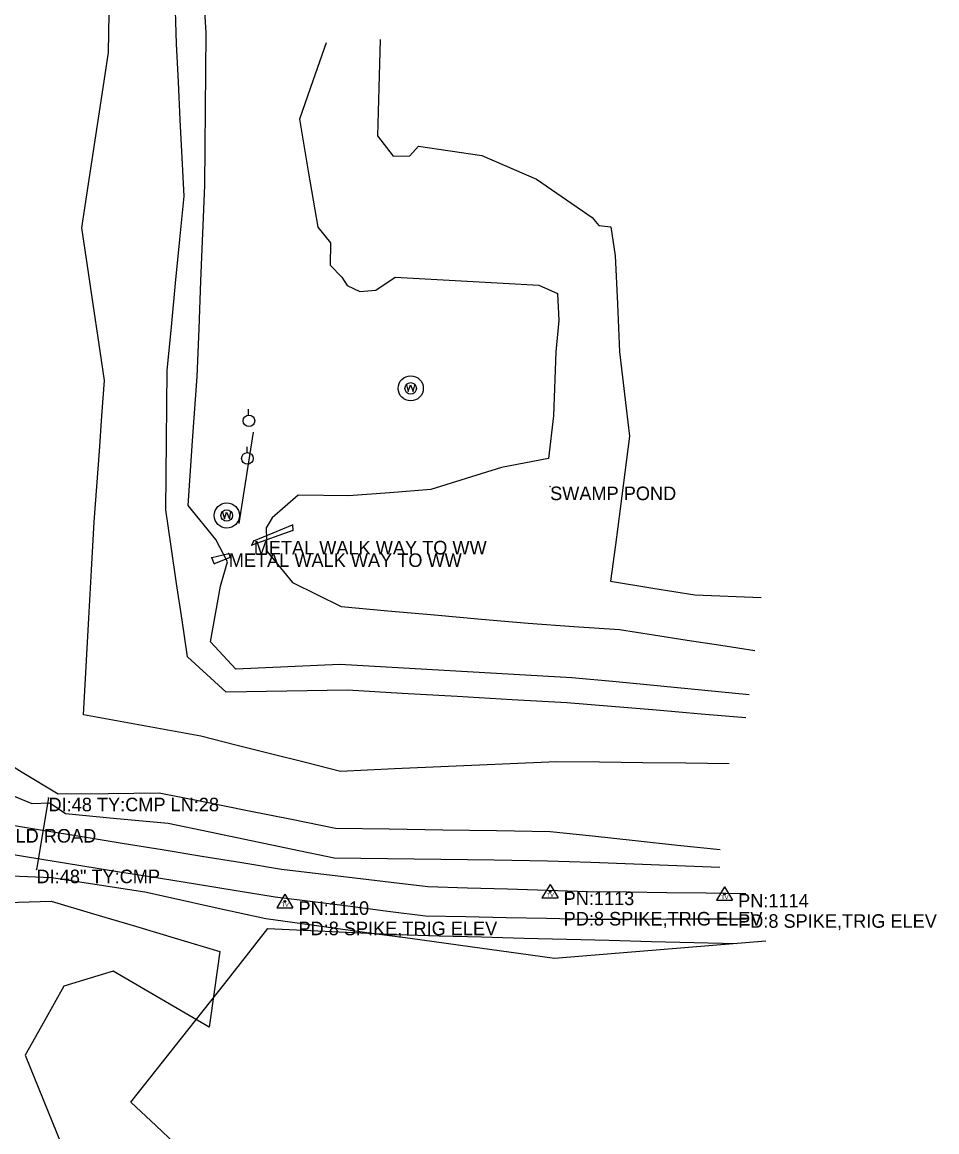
# Model space of a CAD drawing. Extents: x 1445297 to 1476720, y 2042269 to 2057889.
# Drawn here: x 1446166.6 to 1446503.5, y 2044126.9 to 2044535.6 of the extents above; entities that cross this region are included whole.
import ezdxf

# ---------------------------------------------------------------- set-up
doc = ezdxf.new("R2010")
doc.units = 0
for name, color, linetype in [('S_DITCHLINE', 7, 'Continuous'), ('S_DRG_PT_SYM', 7, 'Continuous'), ('S_DRIVEWAY', 7, 'Continuous'), ('S_MISC_STRUCTURES', 7, 'Continuous'), ('S_MISC_STRUCTURES_ANNOT', 7, 'Continuous'), ('S_MSC_PT_SYM', 7, 'Continuous'), ('S_SECONDARY_CTL', 7, 'Continuous'), ('S_SECONDARY_CTL_ANNOT', 7, 'Continuous'), ('S_SIDE_DRAIN', 7, 'Continuous'), ('S_SIDE_DRAIN_ANNOT', 7, 'Continuous'), ('S_STREAM', 7, 'Continuous'), ('S_SURVEY_TEXT_ANNOT', 7, 'Continuous'), ('S_TREE', 7, 'Continuous'), ('S_UTILITY_POLE', 7, 'Continuous'), ('S_WATER_WELL', 7, 'Continuous')]:
    doc.layers.add(name, color=color, linetype=linetype)

msp = doc.modelspace()

# ---------------------------------------------------------------- linework, layer by layer
at = {"layer": 'S_DITCHLINE'}
for points in [[(1446426.97, 2044262.5), (1446411.07, 2044262.69), (1446395.16, 2044262.88), (1446379.26, 2044263.07), (1446363.35, 2044263.26), (1446343.47, 2044262.37), (1446323.58, 2044261.47), (1446303.7, 2044260.58), (1446283.82, 2044259.69), (1446270.96, 2044262.92), (1446258.11, 2044266.15), (1446245.26, 2044269.38), (1446232.4, 2044272.61), (1446210.83, 2044276.54), (1446189.26, 2044280.46), (1446190.23, 2044298.26), (1446191.19, 2044316.06), (1446192.16, 2044333.85), (1446193.12, 2044351.65), (1446194.09, 2044364.66), (1446195.05, 2044377.67), (1446196.01, 2044390.68), (1446196.98, 2044403.68), (1446194.89, 2044417.75), (1446192.8, 2044431.81), (1446190.7, 2044445.87), (1446188.61, 2044459.94), (1446191.07, 2044476.06), (1446193.52, 2044492.19), (1446195.98, 2044508.31), (1446198.43, 2044524.43), (1446198.76, 2044546.08)], [(1446433.14, 2044279.42), (1446416.67, 2044280.8), (1446400.19, 2044282.18), (1446383.71, 2044283.56), (1446367.23, 2044284.94), (1446347.02, 2044286.09), (1446326.81, 2044287.25), (1446306.6, 2044288.41), (1446286.39, 2044289.56), (1446264.07, 2044289.19), (1446241.76, 2044288.82), (1446227.48, 2044301.91), (1446225.5, 2044315.43), (1446223.52, 2044328.94), (1446221.53, 2044342.46), (1446219.55, 2044355.98), (1446219.67, 2044368.82), (1446219.79, 2044381.66), (1446219.91, 2044394.5), (1446220.04, 2044407.35), (1446221.59, 2044423.41), (1446223.14, 2044439.48), (1446224.69, 2044455.54), (1446226.24, 2044471.6), (1446225.55, 2044485.63), (1446224.86, 2044499.66), (1446224.16, 2044513.69), (1446223.47, 2044527.71), (1446222.82, 2044547.92)], [(1446423.68, 2044230.76), (1446408.02, 2044232.43), (1446392.37, 2044234.11), (1446376.72, 2044235.78), (1446361.06, 2044237.46), (1446341.3, 2044237.77), (1446321.55, 2044238.08), (1446301.79, 2044238.38), (1446282.03, 2044238.69), (1446265.79, 2044241.93), (1446249.55, 2044245.17), (1446233.31, 2044248.42), (1446217.07, 2044251.66), (1446198.45, 2044251.44), (1446179.83, 2044251.23), (1446166.64, 2044259.28), (1446153.45, 2044267.34)], [(1446161.07, 2044211.42), (1446177.35, 2044211.9), (1446192.85, 2044207.25), (1446208.35, 2044202.61), (1446223.85, 2044197.96), (1446239.36, 2044193.31), (1446237.45, 2044179.38), (1446235.53, 2044165.45), (1446217.86, 2044175.79), (1446200.18, 2044186.13), (1446181.98, 2044180.52), (1446174.87, 2044167.83), (1446167.75, 2044155.15), (1446174.36, 2044138.84), (1446180.96, 2044122.53)]]:
    msp.add_lwpolyline(points, dxfattribs=at)
at = {"layer": 'S_DRG_PT_SYM'}
for points in [[(1446176.33, 2044249.98), (1446176.33, 2044250.03), (1446176.33, 2044249.98), (1446176.28, 2044249.98), (1446176.33, 2044249.98), (1446176.33, 2044249.93), (1446176.33, 2044249.98), (1446176.38, 2044249.98)], [(1446171.93, 2044223.49), (1446171.93, 2044223.54), (1446171.93, 2044223.49), (1446171.88, 2044223.49), (1446171.93, 2044223.49), (1446171.93, 2044223.44), (1446171.93, 2044223.49), (1446171.98, 2044223.49)]]:
    msp.add_lwpolyline(points, dxfattribs=at)
at = {"layer": 'S_DRIVEWAY'}
for points in [[(1446120.2, 2044252.54), (1446131.57, 2044246.1), (1446144.72, 2044242.87), (1446159.4, 2044240.47), (1446174.09, 2044238.08), (1446188.77, 2044235.68), (1446203.45, 2044233.29), (1446218.13, 2044230.89), (1446232.81, 2044228.5), (1446247.49, 2044226.1), (1446262.18, 2044223.71), (1446275.63, 2044222.1), (1446289.08, 2044220.5), (1446302.53, 2044218.89), (1446315.98, 2044217.29), (1446330.69, 2044216.84), (1446345.39, 2044216.38), (1446360.1, 2044215.93), (1446374.81, 2044215.47), (1446389.39, 2044215.28), (1446403.98, 2044215.08), (1446418.56, 2044214.89), (1446433.15, 2044214.69)], [(1446121.63, 2044225.44), (1446145.27, 2044231.95), (1446159.59, 2044229.64), (1446173.9, 2044227.34), (1446188.22, 2044225.04), (1446202.53, 2044222.73), (1446216.85, 2044220.43), (1446231.17, 2044218.12), (1446245.48, 2044215.82), (1446259.8, 2044213.52), (1446273.64, 2044211.76), (1446287.48, 2044209.99), (1446301.32, 2044208.23), (1446315.16, 2044206.47), (1446330.01, 2044206.17), (1446344.87, 2044205.87), (1446359.72, 2044205.56), (1446374.57, 2044205.26), (1446389.23, 2044205.3), (1446403.89, 2044205.33), (1446418.55, 2044205.37), (1446433.2, 2044205.41)]]:
    msp.add_lwpolyline(points, dxfattribs=at)
at = {"layer": 'S_MISC_STRUCTURES'}
for p, q in [((1446251.89, 2044344.6), (1446266.14, 2044350.45)), ((1446266.14, 2044350.45), (1446266.29, 2044348.4)), ((1446266.29, 2044348.4), (1446251.17, 2044342.95)), ((1446251.17, 2044342.95), (1446251.89, 2044344.6)), ((1446236.49, 2044338.49), (1446242.71, 2044339.98)), ((1446237.36, 2044336.14), (1446236.49, 2044338.49)), ((1446243.28, 2044338.44), (1446237.36, 2044336.14)), ((1446242.71, 2044339.98), (1446243.28, 2044338.44))]:
    msp.add_line(p, q, dxfattribs=at)
at = {"layer": 'S_MSC_PT_SYM'}
for points in [[(1446361.05, 2044364.59), (1446361.05, 2044364.64), (1446361.05, 2044364.59), (1446361, 2044364.59), (1446361.05, 2044364.59), (1446361.05, 2044364.54), (1446361.05, 2044364.59), (1446361.1, 2044364.59)], [(1446266.14, 2044350.45), (1446266.14, 2044350.5), (1446266.14, 2044350.45), (1446266.09, 2044350.45), (1446266.14, 2044350.45), (1446266.14, 2044350.4), (1446266.14, 2044350.45), (1446266.19, 2044350.45)], [(1446266.29, 2044348.4), (1446266.29, 2044348.45), (1446266.29, 2044348.4), (1446266.24, 2044348.4), (1446266.29, 2044348.4), (1446266.29, 2044348.35), (1446266.29, 2044348.4), (1446266.34, 2044348.4)], [(1446251.17, 2044342.95), (1446251.17, 2044343), (1446251.17, 2044342.95), (1446251.12, 2044342.95), (1446251.17, 2044342.95), (1446251.17, 2044342.9), (1446251.17, 2044342.95), (1446251.22, 2044342.95)], [(1446251.89, 2044344.6), (1446251.89, 2044344.65), (1446251.89, 2044344.6), (1446251.84, 2044344.6), (1446251.89, 2044344.6), (1446251.89, 2044344.55), (1446251.89, 2044344.6), (1446251.94, 2044344.6)], [(1446236.49, 2044338.49), (1446236.49, 2044338.54), (1446236.49, 2044338.49), (1446236.44, 2044338.49), (1446236.49, 2044338.49), (1446236.49, 2044338.44), (1446236.49, 2044338.49), (1446236.54, 2044338.49)], [(1446242.71, 2044339.98), (1446242.71, 2044340.03), (1446242.71, 2044339.98), (1446242.66, 2044339.98), (1446242.71, 2044339.98), (1446242.71, 2044339.93), (1446242.71, 2044339.98), (1446242.76, 2044339.98)], [(1446243.28, 2044338.44), (1446243.28, 2044338.49), (1446243.28, 2044338.44), (1446243.23, 2044338.44), (1446243.28, 2044338.44), (1446243.28, 2044338.39), (1446243.28, 2044338.44), (1446243.33, 2044338.44)], [(1446237.36, 2044336.14), (1446237.36, 2044336.19), (1446237.36, 2044336.14), (1446237.31, 2044336.14), (1446237.36, 2044336.14), (1446237.36, 2044336.09), (1446237.36, 2044336.14), (1446237.41, 2044336.14)]]:
    msp.add_lwpolyline(points, dxfattribs=at)
at = {"layer": 'S_SECONDARY_CTL'}
for p, q in [((1446263.37, 2044214.44), (1446260.36, 2044209.48)), ((1446263.37, 2044214.44), (1446266.32, 2044209.48)), ((1446361.04, 2044218.02), (1446358.03, 2044213.07)), ((1446361.04, 2044218.02), (1446363.98, 2044213.07)), ((1446425.29, 2044217.18), (1446422.28, 2044212.23)), ((1446425.29, 2044217.18), (1446428.24, 2044212.23)), ((1446358.03, 2044213.07), (1446363.98, 2044213.07)), ((1446422.28, 2044212.23), (1446428.24, 2044212.23)), ((1446260.36, 2044209.48), (1446266.32, 2044209.48))]:
    msp.add_line(p, q, dxfattribs=at)
for centre, radius in [((1446361.04, 2044215.41), 0.311), ((1446361.04, 2044215.41), 0.183), ((1446361.04, 2044215.41), 0.103), ((1446425.29, 2044214.57), 0.311), ((1446425.29, 2044214.57), 0.183), ((1446425.29, 2044214.57), 0.103), ((1446263.37, 2044211.83), 0.311), ((1446263.37, 2044211.83), 0.183), ((1446263.37, 2044211.83), 0.103)]:
    msp.add_circle(centre, radius, dxfattribs=at)
at = {"layer": 'S_SIDE_DRAIN'}
msp.add_line((1446176.33, 2044249.98), (1446171.93, 2044223.49), dxfattribs=at)
at = {"layer": 'S_STREAM'}
for points in [[(1446434.39, 2044287.91), (1446418.05, 2044289.48), (1446401.7, 2044291.05), (1446385.35, 2044292.62), (1446369.01, 2044294.18), (1446347.67, 2044295.4), (1446326.33, 2044296.62), (1446304.99, 2044297.83), (1446283.65, 2044299.05), (1446264.46, 2044298.19), (1446245.26, 2044297.33), (1446236.03, 2044307.42), (1446239.68, 2044327.94), (1446242.24, 2044336.82), (1446237.92, 2044345.13), (1446227.77, 2044357.64), (1446229.41, 2044381.4), (1446231.05, 2044405.16), (1446231.76, 2044422.75), (1446232.48, 2044440.34), (1446233.19, 2044457.93), (1446233.9, 2044475.51), (1446234.03, 2044489.56), (1446234.15, 2044503.61), (1446234.27, 2044517.66), (1446234.4, 2044531.71), (1446233.18, 2044551.58)], [(1446298.49, 2044529.24), (1446297.99, 2044511.49), (1446297.49, 2044493.73), (1446303.31, 2044486.3), (1446309.44, 2044486.36), (1446312.59, 2044489.99), (1446335.95, 2044486.5), (1446356.05, 2044477.88), (1446376.58, 2044463.71), (1446379.03, 2044460.71), (1446383.47, 2044460.32), (1446384.99, 2044449.52), (1446385.81, 2044431.84), (1446386.64, 2044414.17), (1446388.46, 2044398.66), (1446390.28, 2044383.15), (1446388.55, 2044369.79), (1446386.82, 2044356.44), (1446385.08, 2044343.09), (1446383.35, 2044329.73), (1446398.87, 2044327.22), (1446414.4, 2044324.7), (1446438.84, 2044323.79)], [(1446278.52, 2044528.07), (1446273.62, 2044513.98), (1446268.73, 2044499.89), (1446272.11, 2044480.03), (1446275.5, 2044460.17), (1446280.17, 2044454.4), (1446280.11, 2044446.2), (1446284.41, 2044441.7), (1446286.34, 2044438.69), (1446290.99, 2044436.47), (1446296.81, 2044436.99), (1446304.02, 2044441.67), (1446317.25, 2044440.95), (1446330.49, 2044440.22), (1446343.72, 2044439.5), (1446356.96, 2044438.77), (1446363.78, 2044435.76), (1446364.25, 2044425.74), (1446363.21, 2044414.23), (1446362.36, 2044390.62), (1446360.51, 2044374.92), (1446343.1, 2044371.56), (1446330.13, 2044367.51), (1446317.16, 2044363.47), (1446301.97, 2044362.31), (1446286.78, 2044361.15), (1446268.29, 2044361.38), (1446258.67, 2044353.06), (1446256.44, 2044349.36), (1446256.74, 2044340.8), (1446266.13, 2044329.2), (1446284.07, 2044320.43), (1446301.29, 2044318.88), (1446318.51, 2044317.33), (1446335.73, 2044315.78), (1446352.95, 2044314.23), (1446369.79, 2044313.07), (1446386.62, 2044311.91), (1446399.07, 2044309.98), (1446411.52, 2044308.05), (1446423.97, 2044306.12), (1446436.41, 2044304.18)], [(1446251.65, 2044384.59), (1446246.43, 2044350.97)], [(1446423.57, 2044224.29), (1446407.71, 2044224.88), (1446391.85, 2044225.48), (1446375.99, 2044226.07), (1446360.13, 2044226.66), (1446340.46, 2044226.93), (1446320.8, 2044227.21), (1446301.14, 2044227.48), (1446281.48, 2044227.75), (1446266.21, 2044230.93), (1446250.95, 2044234.11), (1446235.68, 2044237.29), (1446220.42, 2044240.47), (1446201.47, 2044242.26), (1446182.53, 2044244.04), (1446176.83, 2044248), (1446170.36, 2044247.78), (1446150.03, 2044256.1)], [(1446067.35, 2044152.66), (1446079.37, 2044146.37), (1446095.21, 2044141.8), (1446111.04, 2044137.24), (1446121.92, 2044144.5), (1446129.16, 2044155.12), (1446130.43, 2044173.5), (1446131.69, 2044191.88), (1446136.83, 2044206.94), (1446141.97, 2044222), (1446159.7, 2044221.3), (1446177.43, 2044220.59)], [(1446177.43, 2044220.59), (1446211.76, 2044215.37)], [(1446211.76, 2044215.37), (1446221.3, 2044213.2), (1446238.86, 2044209.35), (1446256.42, 2044205.5), (1446269.69, 2044203.67), (1446282.97, 2044201.85), (1446296.25, 2044200.02), (1446309.53, 2044198.19), (1446322.8, 2044196.37), (1446336.08, 2044194.54), (1446349.36, 2044192.71), (1446362.64, 2044190.88), (1446382.09, 2044192.49), (1446401.54, 2044194.1), (1446421, 2044195.71), (1446440.45, 2044197.32)]]:
    msp.add_lwpolyline(points, dxfattribs=at)
at = {"layer": 'S_TREE'}
msp.add_lwpolyline([(1446225.2, 2044120.44), (1446215.93, 2044129.15), (1446206.67, 2044137.85), (1446216.01, 2044149.6), (1446225.36, 2044161.36), (1446233.3, 2044171.47), (1446241.24, 2044181.59), (1446249.18, 2044191.7), (1446257.13, 2044201.81), (1446280.83, 2044200.67), (1446304.53, 2044199.54), (1446320.18, 2044199.13), (1446335.83, 2044198.71), (1446351.48, 2044198.3), (1446367.13, 2044197.89), (1446382.77, 2044197.48), (1446398.42, 2044197.07), (1446414.07, 2044196.66), (1446429.72, 2044196.25)], dxfattribs=at)
at = {"layer": 'S_UTILITY_POLE'}
for p, q in [((1446250.02, 2044390.97), (1446250.02, 2044393.07)), ((1446249.44, 2044377.1), (1446249.44, 2044379.21))]:
    msp.add_line(p, q, dxfattribs=at)
for centre in [(1446250.14, 2044388.82), (1446249.57, 2044374.96)]:
    msp.add_circle(centre, 2.13, dxfattribs=at)
at = {"layer": 'S_WATER_WELL'}
for p, q in [((1446308.17, 2044402.03), (1446308.82, 2044399.55)), ((1446308.82, 2044399.55), (1446309.64, 2044402.03)), ((1446309.64, 2044402.03), (1446310.68, 2044399.55)), ((1446310.68, 2044399.55), (1446311.27, 2044402.07)), ((1446240.42, 2044355.19), (1446241.08, 2044352.71)), ((1446241.08, 2044352.71), (1446241.89, 2044355.19)), ((1446241.89, 2044355.19), (1446242.94, 2044352.71)), ((1446242.94, 2044352.71), (1446243.52, 2044355.23))]:
    msp.add_line(p, q, dxfattribs=at)
for centre, radius in [((1446309.73, 2044400.77), 4.63), ((1446309.7, 2044400.77), 2.13), ((1446241.98, 2044353.93), 4.63), ((1446241.95, 2044353.93), 2.13)]:
    msp.add_circle(centre, radius, dxfattribs=at)

# ---------------------------------------------------------------- texts
at = {"layer": 'S_MISC_STRUCTURES_ANNOT'}
for p in [(1446251.89, 2044339.6), (1446242.71, 2044334.98)]:
    msp.add_text('METAL WALK WAY TO WW', height=5, dxfattribs=at).set_placement(p)
at = {"layer": 'S_SECONDARY_CTL'}
for p in [(1446359.83, 2044213.4), (1446262.17, 2044209.81), (1446424.09, 2044212.56)]:
    msp.add_text('TV', height=1.5, dxfattribs=at).set_placement(p)
at = {"layer": 'S_SECONDARY_CTL_ANNOT'}
for s, p in [('PN:1113', (1446366.04, 2044210.41)), ('PN:1114', (1446430.29, 2044209.57)), ('PN:1110', (1446268.37, 2044206.83)), ('PD:8 SPIKE,TRIG ELEV', (1446366.04, 2044202.91)), ('PD:8 SPIKE,TRIG ELEV', (1446430.29, 2044202.07)), ('PD:8 SPIKE,TRIG ELEV', (1446268.37, 2044199.33))]:
    msp.add_text(s, height=5, dxfattribs=at).set_placement(p)
at = {"layer": 'S_SIDE_DRAIN_ANNOT'}
for s, p in [('DI:48 TY:CMP LN:28', (1446176.33, 2044244.98)), ('DI:48" TY:CMP', (1446171.93, 2044218.49))]:
    msp.add_text(s, height=5, dxfattribs=at).set_placement(p)
at = {"layer": 'S_SURVEY_TEXT_ANNOT'}
for s, p in [('SWAMP POND', (1446361.05, 2044359.59)), ('DIRT FIELD ROAD', (1446136.33, 2044233.45))]:
    msp.add_text(s, height=5, dxfattribs=at).set_placement(p)

doc.saveas('drawing.dxf')
